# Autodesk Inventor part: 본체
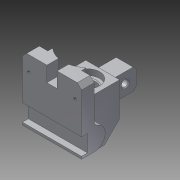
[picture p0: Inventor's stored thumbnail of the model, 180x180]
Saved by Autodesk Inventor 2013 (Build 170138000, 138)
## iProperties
Created: 2016-11
Part Number: 본체
Material: 알루미늄 6061
Document SubType Name: Modeling
Designer: Administrator
Density: 2.71 g/cm^3
Mass: 473.15 g
Surface Area: 319.63 cm^2
Volume: 174.594 cm^3
Author: Administrator
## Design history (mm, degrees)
sketch "스케치1"
  geometry: L1 (-24, 45)-(24, 45); L2 (24, 45)-(24, -27); L3 (6, -45)-(-20, -45); L4 (-24, -41)-(-24, 45); L5 (-24, 45)-(24, -45); L6 (24, 45)-(-24, -45); L7 (24, -27)-(6, -45); L8 (-24, -41)-(-20, -45); 1 further point
  constraints: 16 end point, 4 point on line, 2 midpoint, 2 parallel, 1 horizontal, 1 perpendicular
  dimensions: "d0" = 90 distance of L1.end L5.end; "d2" = 48 distance of L5.end L6.end; "d3" = 18 distance of L2.end L5.end; "d4" = 18 distance of L3.start L5.end (= d3); "d5" = 4 distance of L4.start L6.end; "d6" = 4 distance of L3.end L6.end (= d5)
extrude "돌출1" new body sketch "스케치1" stored distance "d7" = 40; taper "d8" = 0 deg
sketch "스케치2"
  geometry: L1 (24, 45)-(24, -27) reference; L2 (24, -27)-(6, -45) reference; L3 (6, -45)-(-20, -45) reference; L4 (-20, -45)-(-24, -41) reference; L5 (-24, -41)-(-24, 45) reference; L6 (-24, 45)-(24, 45) reference; L7 (-21, -31)-(-36, -31); L8 (-36, 45)-(-21, 45); L9 (-36, -28)-(-29, -28); L10 (-29, -28)-(-29, -8); L11 (-29, -8)-(-36, -8); L12 (-36, -31)-(-36, -28); L13 (-36, -8)-(-36, 45); L14 (-21, 45)-(-21, -0.708); A1 r 13 centre (-21, -18) between (-21, -31) and (-17.389, -5.512); A2 r 5 centre (-16, -0.708) between (-21, -0.708) and (-17.389, -5.512); 4 further points
  constraints: 16 end point, 6 perpendicular, 5 point on circle, 4 point on line, 2 centre point, 2 tangent, 1 horizontal, 1 parallel
  dimensions: "d9" = 90 distance between parallel lines of L3 L8; "d10" = 76 distance of L7.end L8.start; "d14" = 20 distance of L9.end L10.end; "d15" = 3 distance of L7.end L9.start; "d17" = 76 distance between parallel lines of L8 L7; "d19" = 7 distance between parallel lines of L10 L12; "d85" = 26 diameter of A1; "d86" = 12 distance between parallel lines of L5 L13; "d87" = 15 distance of L8.start L8.end; "d88" = 15 distance of L7.start L7.end; "d89" = 5 radius of A2; "d90" = 45.70838 distance of L8.end L14.end
extrude "돌출2" join sketch "스케치2" stored distance "d20" = 70; taper "d21" = 0 deg
sketch "스케치3"
  geometry: L1 (-45, 6)-(-45, -20) reference; L2 (45, 24)-(13, 24); L3 (13, 24)-(13, -16); L4 (13, -16)-(45, -16); L5 (45, -16)-(45, 24); L6 (-27, 24)-(45, 24) reference; L7 (45, 24)-(45, -21) reference; L8 (-31, -36)-(-31, -24) reference; L9 (-28, -36)-(-31, -36) reference; L10 (-28, -29)-(-28, -36) reference; L11 (-8, -29)-(-28, -29) reference; L12 (-8, -36)-(-8, -29) reference; L13 (45, -36)-(-8, -36) reference; L14 (45, -21)-(45, -36) reference; L15 (-45, 6)-(-27, 24) reference; L16 (-45, -20)-(-45, 6) reference; L17 (-41, -24)-(-45, -20) reference; L18 (-31, -24)-(-41, -24) reference; L19 (-0.708, -21)-(45, -21) reference; L20 (-31, -24)-(-31, -21) reference; A1 r 5 centre (-0.708, -16) between (-5.512, -17.389) and (-0.708, -21) reference; A2 r 13 centre (-18, -21) between (-5.512, -17.389) and (-31, -21) reference; 1 further point
  constraints: 8 end point, 2 parallel, 1 horizontal, 1 perpendicular
  dimensions: "d22" = 20 distance between parallel lines of L13 L4; "d23" = 58 distance between parallel lines of L1 L3
extrude "돌출3" cut sketch "스케치3" stored distance "d24" = 70; taper "d25" = 0 deg
fillet "모깎기1" dims "d26" = 3
sketch "스케치4"
  geometry: L1 (0, 0)-(40, 0) reference; L2 (40, 0)-(40, -26) reference; L3 (40, 0)-(40, -26) reference; L4 (40, -26)-(0, -26) reference; L5 (0, -26)-(0, 0) reference; L6 (0, 0)-(40, 0) reference; L7 (55, -42)-(-15, -42) reference; L8 (0, -30)-(40, -30) reference; C1 r 10 at (20, 0); 3 further points
  constraints: 2 midpoint, 2 vertical alignment, 1 centre point
  dimensions: "d27" = 20 diameter of C1; "d29" = 30 distance from line of C1.centre L8; "d30" = 20 distance from line of L2 C1.centre
extrude "돌출4" cut sketch "스케치4" distance "d31" = 70; taper "d32" = 0 deg
sketch "스케치5"
  geometry: C1 r 10 at (20, -18) reference; C2 r 14.5 at (20, -18); 1 further point
  constraints: 1 centre point, 1 coincident
  dimensions: "d33" = 29 diameter of C2
extrude "돌출5" cut sketch "스케치5" distance "d34" = 7; taper "d35" = 0 deg
chamfer "모따기1" distance "d36" = 1; stored, may be unused: second distance "d37" = 2, angle "d38" = 45 deg
sketch "스케치6"
  geometry: L1 (16, 5)-(17, 6) reference; L2 (17, 6)-(20.5, 6) reference; L3 (20.5, 6)-(20.5, 13) reference; L4 (20.5, 13)-(24, 13) reference; L5 (24, 13)-(24, -27) reference; L6 (24, -27)-(16, -35) reference; L7 (16, -35)-(16, 5) reference; L8 (-24, -31)-(-36, -31) reference; L9 (-36, -31)-(-36, -28) reference; L10 (-36, -28)-(-29, -28) reference; L11 (-29, -28)-(-29, -8) reference; L12 (-29, -8)-(-36, -8) reference; L13 (-36, -8)-(-36, 45) reference; L14 (-36, 45)-(-16, 45) reference; L15 (-16, 45)-(-16, 16) reference; L16 (-13, 13)-(-8.5, 13) reference; L17 (-8.5, 13)-(-8.5, 6) reference; L18 (-8.5, 6)-(-5, 6) reference; L19 (-5, 6)-(-4, 5) reference; L20 (-4, 5)-(-4, -45) reference; L21 (-4, -45)-(-20, -45) reference; L22 (-20, -45)-(-24, -41) reference; L23 (-24, -41)-(-24, -31) reference; L24 (24, -17)-(50, -17); L25 (54, -13)-(54, 4); L26 (50, 8)-(24, 8); L27 (24, 8)-(24, -17); L28 (50, 8)-(54, 4); L29 (54, -13)-(50, -17); C1 r 4 at (41, -4.5); A1 r 3 centre (-13, 16) between (-16, 16) and (-13, 13) reference; 3 further points
  constraints: 12 end point, 5 point on line, 2 parallel, 1 centre point, 1 horizontal, 1 perpendicular
  dimensions: "d39" = 90 distance between parallel lines of L13 L25; "d40" = 25 distance of point (54, -17) point (54, 8); "d41" = 5 distance between parallel lines of L26 L4; "d42" = 4 distance of L26.start point (54, 8); "d43" = 4 distance of L25.end point (54, 8) (= d42); "d44" = 4 distance of L25.start point (54, -17) (= d42); "d45" = 4 distance of L24.end point (54, -17) (= d44); "d46" = 8 diameter of C1; "d47" = 12.5 distance from line of L24 C1.centre; "d48" = 77 distance from line of L13 C1.centre
extrude "돌출6" join sketch "스케치6" stored distance "d49" = 20; taper "d50" = 0 deg
fillet "모깎기2" dims "d51" = 3
chamfer "모따기2" distance "d52" = 1; stored, may be unused: second distance "d53" = 2, angle "d54" = 45 deg
sketch "스케치7"
  geometry: L1 (0, 0)-(70, 0) reference; L2 (70, 15)-(70, 0) reference; L3 (70, 0)-(0, 0) reference; L4 (0, 0)-(0, 15) reference; L5 (15, 15)-(15, 20) reference; L6 (15, 20)-(55, 20) reference; L7 (55, 20)-(55, 15) reference; L8 (70, 15)-(70, 0) reference; L9 (70, 0)-(0, 0) reference; L10 (0, 0)-(0, 15) reference; L11 (15, 15)-(15, 20) reference; L12 (15, 20)-(55, 20) reference; L13 (55, 20)-(55, 15) reference; L14 (70, 15)-(70, 0) reference; L15 (70, 0)-(0, 0) reference; L16 (0, 0)-(0, 15) reference; L17 (15, 15)-(15, 20) reference; L18 (15, 20)-(55, 20) reference; L19 (55, 20)-(55, 15) reference; L20 (55, 15)-(70, 15) reference; L21 (0, 15)-(15, 15) reference; L22 (55, 15)-(70, 15) reference; L23 (0, 15)-(15, 15) reference; L24 (55, 15)-(70, 15) reference; L25 (0, 15)-(15, 15) reference; C1 r 29 at (35, 42); 1 further point
  constraints: 1 centre point
  dimensions: "d55" = 58 diameter of C1; "d56" = 0 horizontal distance of C1.centre point (35, 36); "d57" = 42 distance from line of L1 C1.centre
extrude "돌출7" cut sketch "스케치7" distance "d58" = 18; taper "d59" = 0 deg
sketch "스케치8"
  geometry: L1 (0, 0)-(70, 0) reference; L2 (29, 0)-(41, 0); L3 (41, 0)-(41, 19.225); L4 (41, 19.225)-(29, 19.225); L5 (29, 19.225)-(29, 0); A1 r 29 centre (35, 42) between (16.106, 20) and (53.894, 20) reference; 1 further point
  constraints: 8 end point, 2 parallel, 1 horizontal, 1 perpendicular
  dimensions: "d60" = 12 distance of L2.start L2.end; "d62" = 6 distance from line of L3 A1.centre; "d63" = 0 distance between parallel lines of L1 L2; "d64" = 19.22497 distance between parallel lines of L1 L4
extrude "돌출8" cut sketch "스케치8" distance "d65" = 18; taper "d66" = 0 deg
chamfer "모따기3" distance "d67" = 5; stored, may be unused: second distance "d68" = 2, angle "d69" = 45 deg
sketch "스케치10"
  geometry: L1 (13, -13)-(13, 24) reference; L2 (13, 24)-(-27, 24) reference; 2 further points
  constraints: 1 other
  dimensions: "d79" = 25 distance from line of L1 point (-12, 6); "d80" = 18 distance from line of L2 point (-12, 6)
feature "엠보싱1" sketch "스케치10" dims "d9" = 90, "d10" = 76, "d14" = 20, "d15" = 3, "d17" = 76, "d19" = 7, "d81" = 0.5, "d82" = 0, "d85" = 26, "d86" = 12, "d87" = 15, "d88" = 15, "d89" = 5, "d90" = 45.70838
sketch "스케치12"
  geometry: 3 further points
  dimensions: "d91" = 27.5 horizontal distance of point (-20, -0.708) point (7.5, -27.708); "d92" = 18 vertical distance of point (0, -45.708) point (7.5, -27.708)
hole "구멍2" sketch "스케치12" at (7.5, -27.708) diameter "d93" = 3.242; stored, may be unused: countersink angle "d97" = 90 deg, drill point angle "d99" = 118 deg; dims "d94" = 6, "d95" = 4, "d96" = 2, "d98" = 8
sketch "스케치13"
  geometry: 1 further point
node "솔리드1"
mirror "대칭2"
node "절단 모서리 투영1"
node "절단 모서리 투영2"
node "절단 모서리 투영3"
node "절단 모서리 투영4"
node "절단 모서리 투영5"
node "절단 모서리 투영6"
node "절단 모서리 투영7"
other parameters: "d11" = 15
